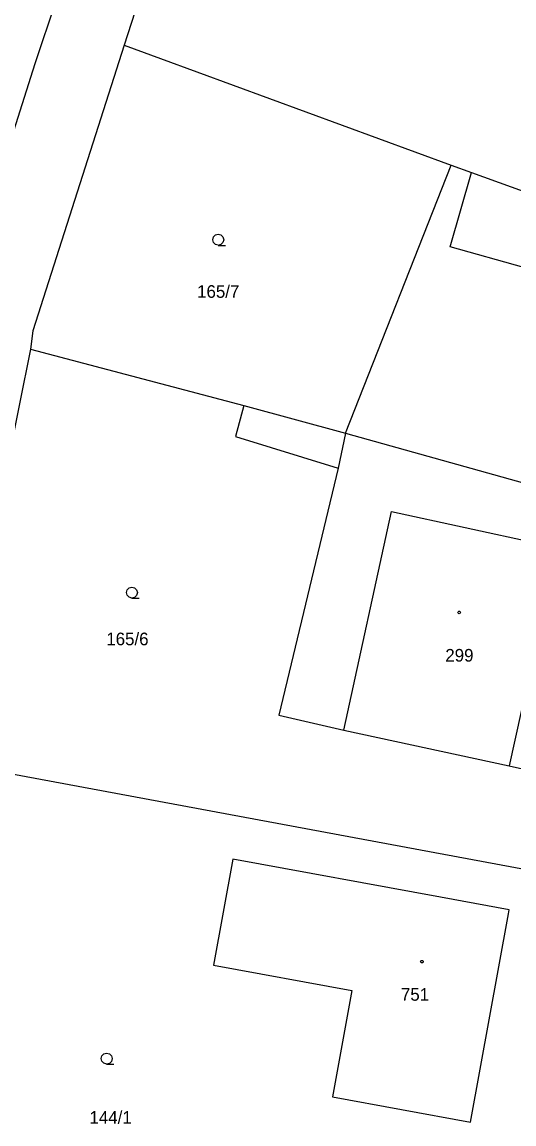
# Model space of a CAD drawing. Extents: x -757994 to -755874, y -1047691 to -1046119.
# Drawn here: x -756727.1 to -756694, y -1046822.2 to -1046748.1 of the extents above; entities that cross this region are included whole.
import ezdxf

# ---------------------------------------------------------------- set-up
doc = ezdxf.new("R2010")
doc.units = 0
doc.layers.add('katastrální mapa', color=7, linetype='Continuous')

msp = doc.modelspace()

# ---------------------------------------------------------------- linework, layer by layer
at = {"layer": 'katastrální mapa'}
for p, q in [((-756719.49, -1046747.41), (-756720.21, -1046749.64)), ((-756720.21, -1046749.64), (-756726.36, -1046768.86)), ((-756720.21, -1046749.64), (-756698.22, -1046757.71)), ((-756705.31, -1046775.74), (-756698.22, -1046757.71)), ((-756698.22, -1046757.71), (-756696.85, -1046758.2)), ((-756698.28, -1046763.19), (-756696.85, -1046758.2)), ((-756696.85, -1046758.2), (-756691.4, -1046760.18)), ((-756693.31, -1046764.59), (-756698.28, -1046763.19)), ((-756726.36, -1046768.86), (-756726.51, -1046770.09)), ((-756726.51, -1046770.09), (-756732.14, -1046797.84)), ((-756726.51, -1046770.09), (-756712.16, -1046773.87)), ((-756712.16, -1046773.87), (-756712.73, -1046775.96)), ((-756712.16, -1046773.87), (-756705.31, -1046775.74)), ((-756712.73, -1046775.96), (-756705.82, -1046778.1)), ((-756705.31, -1046775.74), (-756705.82, -1046778.1)), ((-756705.31, -1046775.74), (-756686.09, -1046781.1)), ((-756705.82, -1046778.1), (-756709.81, -1046794.72)), ((-756705.43, -1046795.72), (-756702.22, -1046781.02)), ((-756702.22, -1046781.02), (-756691.08, -1046783.43)), ((-756691.08, -1046783.43), (-756694.31, -1046798.13)), ((-756709.81, -1046794.72), (-756705.43, -1046795.72)), ((-756705.43, -1046795.72), (-756694.31, -1046798.13)), ((-756732.14, -1046797.84), (-756691, -1046805.51)), ((-756694.31, -1046798.13), (-756689.72, -1046799.14)), ((-756712.9, -1046804.41), (-756714.2, -1046811.54)), ((-756698.92, -1046806.97), (-756712.9, -1046804.41)), ((-756694.31, -1046807.82), (-756698.92, -1046806.97)), ((-756694.36, -1046808.09), (-756694.31, -1046807.82)), ((-756696.92, -1046822.1), (-756694.36, -1046808.09)), ((-756714.2, -1046811.54), (-756704.9, -1046813.24)), ((-756704.9, -1046813.24), (-756706.2, -1046820.4)), ((-756706.2, -1046820.4), (-756696.92, -1046822.1))]:
    msp.add_line(p, q, dxfattribs=at)
for points in [[(-756731.44, -1046768.82), (-756730.294, -1046764.517), (-756728.998, -1046759.945), (-756727.631, -1046755.393), (-756726.194, -1046750.862), (-756724.78, -1046746.64), (-756723.159, -1046741.998), (-756721.186, -1046736.669), (-756719.115, -1046731.377), (-756716.948, -1046726.124), (-756714.683, -1046720.913), (-756712.64, -1046716.44)], [(-756713.88, -1046763.09), (-756714.07, -1046763.04), (-756714.205, -1046762.905), (-756714.255, -1046762.72), (-756714.205, -1046762.535), (-756714.07, -1046762.4), (-756713.885, -1046762.35), (-756713.7, -1046762.4), (-756713.565, -1046762.535), (-756713.515, -1046762.725), (-756713.565, -1046762.915), (-756713.7, -1046763.05), (-756713.89, -1046763.1), (-756713.39, -1046763.1)], [(-756719.69, -1046786.83), (-756719.88, -1046786.78), (-756720.015, -1046786.645), (-756720.065, -1046786.46), (-756720.015, -1046786.275), (-756719.88, -1046786.14), (-756719.695, -1046786.09), (-756719.51, -1046786.14), (-756719.375, -1046786.275), (-756719.325, -1046786.465), (-756719.375, -1046786.655), (-756719.51, -1046786.79), (-756719.7, -1046786.84), (-756719.2, -1046786.84)], [(-756721.39, -1046818.19), (-756721.58, -1046818.14), (-756721.715, -1046818.005), (-756721.765, -1046817.82), (-756721.715, -1046817.635), (-756721.58, -1046817.5), (-756721.395, -1046817.45), (-756721.21, -1046817.5), (-756721.075, -1046817.635), (-756721.025, -1046817.825), (-756721.075, -1046818.015), (-756721.21, -1046818.15), (-756721.4, -1046818.2), (-756720.9, -1046818.2)]]:
    msp.add_lwpolyline(points, dxfattribs=at)
for points in [[(-756697.67, -1046787.715), (-756697.62, -1046787.725), (-756697.595, -1046787.77), (-756697.585, -1046787.8), (-756697.595, -1046787.845), (-756697.635, -1046787.88), (-756697.67, -1046787.885), (-756697.715, -1046787.87), (-756697.745, -1046787.84), (-756697.755, -1046787.8), (-756697.745, -1046787.755), (-756697.705, -1046787.72)], [(-756700.18, -1046811.215), (-756700.13, -1046811.225), (-756700.105, -1046811.27), (-756700.095, -1046811.3), (-756700.105, -1046811.345), (-756700.145, -1046811.38), (-756700.18, -1046811.385), (-756700.225, -1046811.37), (-756700.255, -1046811.34), (-756700.265, -1046811.3), (-756700.255, -1046811.255), (-756700.215, -1046811.22)]]:
    msp.add_lwpolyline(points, close=True, dxfattribs=at)

# ---------------------------------------------------------------- texts
for s, p in [('165/7', (-756715.306, -1046766.63)), ('165/6', (-756721.416, -1046790.01)), ('299', (-756698.604, -1046791.11)), ('751', (-756701.591, -1046813.93)), ('144/1', (-756722.549, -1046822.21))]:
    msp.add_text(s, height=0.85, dxfattribs=at).set_placement(p)

doc.saveas('drawing.dxf')
